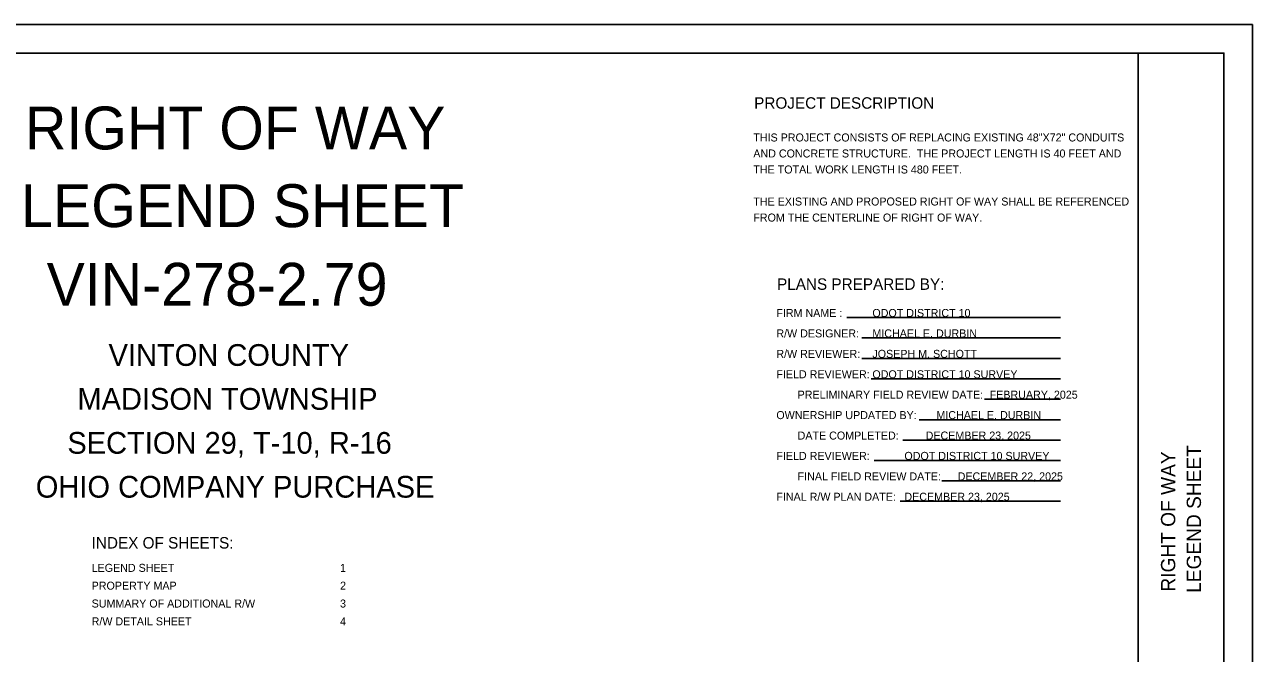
# Model space of a CAD drawing. Extents: x 0 to 34, y 0 to 22.
# Drawn here: x 12.52 to 34, y 11 to 22 of the extents above; entities that cross this region are included whole.
import ezdxf

# ---------------------------------------------------------------- set-up
doc = ezdxf.new("R2010")
doc.units = 0
for name, color, linetype in [('SH_Border', 7, 'Continuous'), ('SH_Cut_Line', 7, 'Continuous'), ('SH_Data', 7, 'Continuous'), ('SH_Text', 7, 'Continuous')]:
    doc.layers.add(name, color=color, linetype=linetype)

msp = doc.modelspace()

# ---------------------------------------------------------------- linework, layer by layer
at = {"layer": 'SH_Border'}
msp.add_line((32, 0.5), (32, 21.5), dxfattribs=at)
msp.add_lwpolyline([(1.5, 21.5), (33.5, 21.5), (33.5, 0.5), (1.5, 0.5)], close=True, dxfattribs=at)
at = {"layer": 'SH_Cut_Line'}
msp.add_lwpolyline([(0, 0), (34, 0), (34, 22), (0, 22)], close=True, dxfattribs=at)
at = {"layer": 'SH_Text'}
for p, q in [((26.903, 16.875), (30.64, 16.875)), ((27.167, 16.518), (30.64, 16.518)), ((27.167, 16.161), (30.64, 16.161)), ((27.331, 15.803), (30.64, 15.803)), ((29.312, 15.446), (30.64, 15.446)), ((28.167, 15.089), (30.64, 15.089)), ((27.882, 14.732), (30.64, 14.732)), ((27.385, 14.375), (30.64, 14.375)), ((28.565, 14.017), (30.64, 14.017)), ((27.836, 13.661), (30.64, 13.661))]:
    msp.add_line(p, q, dxfattribs=at)

# ---------------------------------------------------------------- texts
at = {"layer": 'SH_Data'}
for s, height, p in [('RIGHT OF WAY', 0.75, (12.527, 19.816)), ('LEGEND SHEET', 0.75, (12.458, 18.457)), ('VIN-278-2.79', 0.75, (12.904, 17.082)), ('VINTON COUNTY', 0.38, (13.988, 16.03)), ('MADISON TOWNSHIP', 0.38, (13.443, 15.262)), ('SECTION 29, T-10, R-16', 0.38, (13.267, 14.493)), ('OHIO COMPANY PURCHASE', 0.38, (12.715, 13.725)), ('INDEX OF SHEETS:', 0.2, (13.692, 12.835)), ('LEGEND SHEET', 0.14, (13.692, 12.427)), ('1', 0.14, (18.038, 12.427)), ('PROPERTY MAP', 0.14, (13.692, 12.115)), ('2', 0.14, (18.038, 12.115)), ('SUMMARY OF ADDITIONAL R/W', 0.14, (13.692, 11.803)), ('3', 0.14, (18.038, 11.803)), ('R/W DETAIL SHEET', 0.14, (13.692, 11.491)), ('4', 0.14, (18.038, 11.491))]:
    msp.add_text(s, height=height, dxfattribs=at).set_placement(p)
for s, p in [('LEGEND SHEET', (33.1, 12.06)), ('RIGHT OF WAY', (32.65, 12.082))]:
    msp.add_text(s, height=0.25, rotation=90, dxfattribs=at).set_placement(p)
at = {"layer": 'SH_Text'}
for s, height, p in [('PROJECT DESCRIPTION', 0.2, (25.283, 20.528)), ('THIS PROJECT CONSISTS OF REPLACING EXISTING 48"X72" CONDUITS', 0.14, (25.268, 19.955)), ('AND CONCRETE STRUCTURE.  THE PROJECT LENGTH IS 40 FEET AND', 0.14, (25.268, 19.675)), ('THE TOTAL WORK LENGTH IS 480 FEET.', 0.14, (25.268, 19.395)), ('THE EXISTING AND PROPOSED RIGHT OF WAY SHALL BE REFERENCED', 0.14, (25.268, 18.835)), ('FROM THE CENTERLINE OF RIGHT OF WAY.', 0.14, (25.268, 18.554)), ('PLANS PREPARED BY:', 0.2, (25.683, 17.36)), ('FIRM NAME :', 0.14, (25.671, 16.885)), ('ODOT DISTRICT 10', 0.14, (27.351, 16.885)), ('R/W DESIGNER:', 0.14, (25.671, 16.528)), ('MICHAEL E. DURBIN', 0.14, (27.351, 16.528)), ('R/W REVIEWER:', 0.14, (25.671, 16.17)), ('JOSEPH M. SCHOTT', 0.14, (27.351, 16.17)), ('FIELD REVIEWER:', 0.14, (25.671, 15.813)), ('ODOT DISTRICT 10 SURVEY', 0.14, (27.351, 15.813)), ('PRELIMINARY FIELD REVIEW DATE:', 0.14, (26.043, 15.456)), ('FEBRUARY, 2025', 0.14, (29.403, 15.456)), ('OWNERSHIP UPDATED BY:', 0.14, (25.671, 15.099)), ('MICHAEL E. DURBIN', 0.14, (28.471, 15.099)), ('DATE COMPLETED:', 0.14, (26.043, 14.741)), ('DECEMBER 23, 2025', 0.14, (28.283, 14.741)), ('FIELD REVIEWER:', 0.14, (25.671, 14.385)), ('ODOT DISTRICT 10 SURVEY', 0.14, (27.911, 14.385)), ('FINAL FIELD REVIEW DATE:', 0.14, (26.043, 14.027)), ('DECEMBER 22, 2025', 0.14, (28.843, 14.027)), ('FINAL R/W PLAN DATE:', 0.14, (25.671, 13.671)), ('DECEMBER 23, 2025', 0.14, (27.911, 13.671))]:
    msp.add_text(s, height=height, dxfattribs=at).set_placement(p)

doc.saveas('drawing.dxf')
